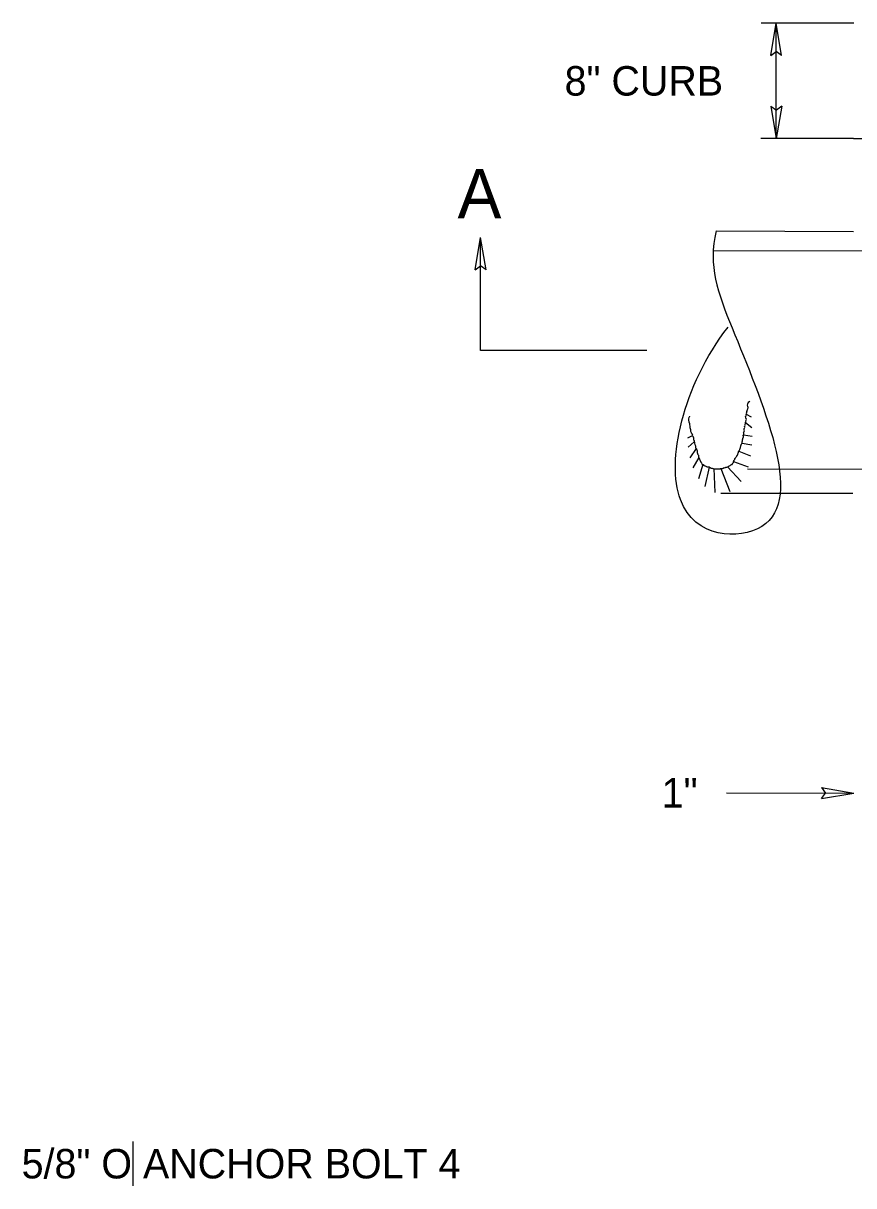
# Model space of a CAD drawing. Extents: x 9.6 to 16.8, y 2.2 to 12.2.
# Drawn here: x 9.553 to 11.244, y 9.293 to 11.658 of the extents above; entities that cross this region are included whole.
import ezdxf

# ---------------------------------------------------------------- set-up
doc = ezdxf.new("R2010")
doc.units = 0
for name, color, linetype in [('DETL-DIMS', 7, 'Continuous'), ('DETL-LINE', 7, 'Continuous'), ('DETL-NOTE', 7, 'Continuous'), ('DETL-PATT', 7, 'Continuous'), ('DETL-TITL', 7, 'Continuous')]:
    doc.layers.add(name, color=color, linetype=linetype)

msp = doc.modelspace()

# ---------------------------------------------------------------- linework, layer by layer
at = {"layer": 'DETL-DIMS'}
for p, q in [((11.2446, 11.6582), (11.0559, 11.6582)), ((11.0754, 11.5924), (11.0865, 11.6582)), ((11.0974, 11.5923), (11.0865, 11.6582)), ((11.0865, 11.4238), (11.0865, 11.6582)), ((11.0754, 11.5924), (11.0864, 11.6005)), ((11.0974, 11.5923), (11.0864, 11.6005)), ((11.0757, 11.4897), (11.0865, 11.4238)), ((11.0757, 11.4897), (11.0867, 11.4814)), ((11.0977, 11.4896), (11.0865, 11.4238)), ((11.0977, 11.4896), (11.0867, 11.4814)), ((11.244, 11.4238), (11.0553, 11.4238)), ((10.4736, 11.1564), (10.4845, 11.2223)), ((10.4845, 10.9927), (10.4845, 11.2223)), ((10.4955, 11.1564), (10.4845, 11.2223)), ((10.4736, 11.1564), (10.4845, 11.1646)), ((10.4955, 11.1564), (10.4845, 11.1646)), ((10.8232, 10.9927), (10.4845, 10.9927)), ((11.1788, 10.103), (11.2446, 10.0919)), ((11.1788, 10.103), (11.187, 10.092)), ((10.9851, 10.0925), (11.2446, 10.0919)), ((11.1787, 10.0811), (11.187, 10.092)), ((11.1787, 10.0811), (11.2446, 10.0919))]:
    msp.add_line(p, q, dxfattribs=at)
at = {"layer": 'DETL-LINE'}
for p, q in [((11.244, 11.4238), (13.5464, 11.4238)), ((10.9642, 11.2356), (11.2435, 11.2348)), ((11.3569, 11.1942), (10.9589, 11.1952)), ((11.361, 10.7504), (11.0276, 10.7513)), ((10.9736, 10.7022), (11.2421, 10.7022))]:
    msp.add_line(p, q, dxfattribs=at)
msp.add_open_spline([(10.9642, 11.2356), (10.9469, 11.165), (10.9878, 11.0558), (11.1018, 10.7869), (11.1027, 10.6013), (10.8291, 10.615), (10.8953, 10.9201), (10.9886, 11.0402)], degree=3, dxfattribs=at)
for points in [[(11.0185, 10.8116), (11.0185, 10.8134), (11.0185, 10.8143), (11.0194, 10.8151), (11.0194, 10.8204), (11.0203, 10.8213), (11.0203, 10.8265), (11.0212, 10.8274), (11.0212, 10.8309), (11.0212, 10.8317), (11.0212, 10.8335), (11.022, 10.8344), (11.022, 10.8378), (11.0229, 10.8396), (11.0229, 10.8422), (11.0238, 10.8431), (11.0238, 10.8465), (11.0247, 10.8475), (11.0238, 10.8483), (11.0247, 10.8492), (11.0247, 10.8596), (11.0255, 10.8596), (11.0255, 10.8631), (11.0264, 10.8649), (11.0264, 10.8675), (11.0273, 10.8675), (11.0264, 10.8693), (11.0273, 10.8693), (11.0273, 10.871), (11.0282, 10.8719), (11.0273, 10.8719), (11.0282, 10.8727), (11.0282, 10.8745), (11.029, 10.8754), (11.029, 10.8762), (11.029, 10.8858), (11.0325, 10.8893)], [(10.9095, 10.8588), (10.9095, 10.8579), (10.9086, 10.8562), (10.9095, 10.844), (10.9112, 10.8335), (10.9121, 10.83), (10.9121, 10.8282), (10.9129, 10.8256), (10.9138, 10.8239), (10.9147, 10.823), (10.9156, 10.8213), (10.9156, 10.8186), (10.9164, 10.8178), (10.9182, 10.8116), (10.9182, 10.8108), (10.9191, 10.8091), (10.9191, 10.8082), (10.9199, 10.8056), (10.9199, 10.8038), (10.9217, 10.7986), (10.9217, 10.7977), (10.9225, 10.7933), (10.9234, 10.7925), (10.9252, 10.7881), (10.9252, 10.7864), (10.926, 10.7829), (10.9269, 10.7811), (10.9278, 10.7794), (10.9278, 10.7776), (10.9287, 10.775), (10.9304, 10.7715), (10.9313, 10.768), (10.9322, 10.7671), (10.9339, 10.7636), (10.9374, 10.7602), (10.9383, 10.7602), (10.9383, 10.7593), (10.94, 10.7584), (10.9418, 10.7576), (10.9444, 10.7567), (10.9453, 10.7558), (10.947, 10.7558), (10.9522, 10.7541), (10.9531, 10.7532), (10.9549, 10.7532), (10.9575, 10.7523), (10.9584, 10.7523), (10.9644, 10.7515), (10.9679, 10.7515), (10.9688, 10.7515), (10.9714, 10.7515), (10.9732, 10.7523), (10.9767, 10.7523), (10.9802, 10.7541), (10.9828, 10.7541), (10.9836, 10.7549), (10.9845, 10.7549), (10.9871, 10.7558), (10.988, 10.7558), (10.9906, 10.7576), (10.9915, 10.7576), (10.9933, 10.7593), (10.995, 10.7602), (10.9976, 10.7619), (10.9976, 10.7628), (10.9993, 10.7645), (10.9993, 10.7663), (11.0002, 10.7671), (11.0002, 10.7689), (11.0011, 10.7698), (11.002, 10.7706), (11.002, 10.7715), (11.0028, 10.7733), (11.0037, 10.7741), (11.0046, 10.7759), (11.0055, 10.7767), (11.0063, 10.7785), (11.0072, 10.7794), (11.0081, 10.7811), (11.0081, 10.782), (11.0098, 10.7855), (11.0098, 10.7872), (11.0116, 10.7898), (11.0124, 10.7916), (11.0124, 10.7925), (11.0133, 10.7942), (11.0133, 10.7951), (11.0142, 10.7977), (11.0142, 10.7986), (11.0151, 10.7995), (11.0151, 10.8012), (11.0159, 10.8021), (11.0168, 10.8047), (11.0168, 10.8064), (11.0177, 10.8082), (11.0177, 10.8108), (11.0185, 10.8116)]]:
    msp.add_spline(points, degree=3, dxfattribs=at)
at = {"layer": 'DETL-NOTE'}
msp.add_line((9.7769, 9.2931), (9.7769, 9.3828), dxfattribs=at)
at = {"layer": 'DETL-PATT'}
for p, q in [((11.0255, 10.8627), (11.0354, 10.8572)), ((11.0238, 10.8457), (11.0369, 10.8356)), ((10.9155, 10.819), (10.9058, 10.8142)), ((11.0195, 10.8205), (11.0373, 10.8184)), ((10.9196, 10.8066), (10.9069, 10.796)), ((10.9231, 10.7928), (10.9104, 10.7738)), ((11.0101, 10.7878), (11.0343, 10.7782)), ((11.0167, 10.804), (11.0367, 10.8004)), ((10.929, 10.7744), (10.9166, 10.7535)), ((10.9995, 10.7665), (11.0291, 10.7558)), ((10.9369, 10.7606), (10.9278, 10.7313)), ((10.95, 10.755), (10.9413, 10.7155)), ((10.9591, 10.7522), (10.9617, 10.7037)), ((10.9733, 10.7524), (10.9921, 10.7057)), ((10.9872, 10.7558), (11.0152, 10.726))]:
    msp.add_line(p, q, dxfattribs=at)

# ---------------------------------------------------------------- texts
at = {"layer": 'DETL-NOTE'}
for s, p in [('8" CURB', (10.6555, 11.511)), ('1"', (10.8532, 10.0625)), ('5/8" O ANCHOR BOLT 4', (9.5501, 9.308))]:
    msp.add_text(s, height=0.06, dxfattribs=at).set_placement(p)
at = {"layer": 'DETL-TITL'}
msp.add_text('A', height=0.1, dxfattribs=at).set_placement((10.4376, 11.2615))

doc.saveas('drawing.dxf')
